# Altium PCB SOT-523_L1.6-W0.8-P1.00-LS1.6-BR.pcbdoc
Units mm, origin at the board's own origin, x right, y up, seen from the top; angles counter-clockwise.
Board outline 14.98 x 14.5 mm, 2 copper layers (Top Layer, Bottom Layer), stack 0 mm thick; 1 components, 0 nets, 3 pads, 0 vias.
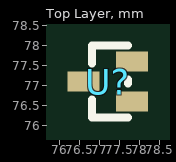
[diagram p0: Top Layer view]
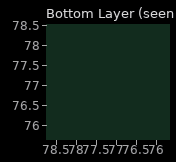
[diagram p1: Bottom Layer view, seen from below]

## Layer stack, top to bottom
Top Layer: signal copper (thickness not stored)
Bottom Layer: signal copper (thickness not stored)

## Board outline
84.826,69.85 69.85,69.85 69.85,84.35 84.826,84.35

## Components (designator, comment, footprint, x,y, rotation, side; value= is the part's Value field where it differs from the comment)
U? "" SOT-523_L1.6-W0.8-P1.00-LS1.6-BR 77.208,77.1 r0 top

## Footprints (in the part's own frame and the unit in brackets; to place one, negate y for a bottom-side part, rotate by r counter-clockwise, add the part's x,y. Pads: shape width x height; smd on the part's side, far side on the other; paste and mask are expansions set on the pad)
SOT-523_L1.6-W0.8-P1.00-LS1.6-BR [mm]
  rect 0.8x0.5 smd: 1(0.608,-0.5) 2(0.608,0.5) 3(-0.608,0)
  silkscreen extent -0.4,-0.9 0.5,0.9

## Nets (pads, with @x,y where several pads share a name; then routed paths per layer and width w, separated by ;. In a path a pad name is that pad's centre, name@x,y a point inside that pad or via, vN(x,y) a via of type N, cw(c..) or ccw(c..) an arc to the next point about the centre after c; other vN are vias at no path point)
pads on no net: U?.1 U?.2 U?.3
